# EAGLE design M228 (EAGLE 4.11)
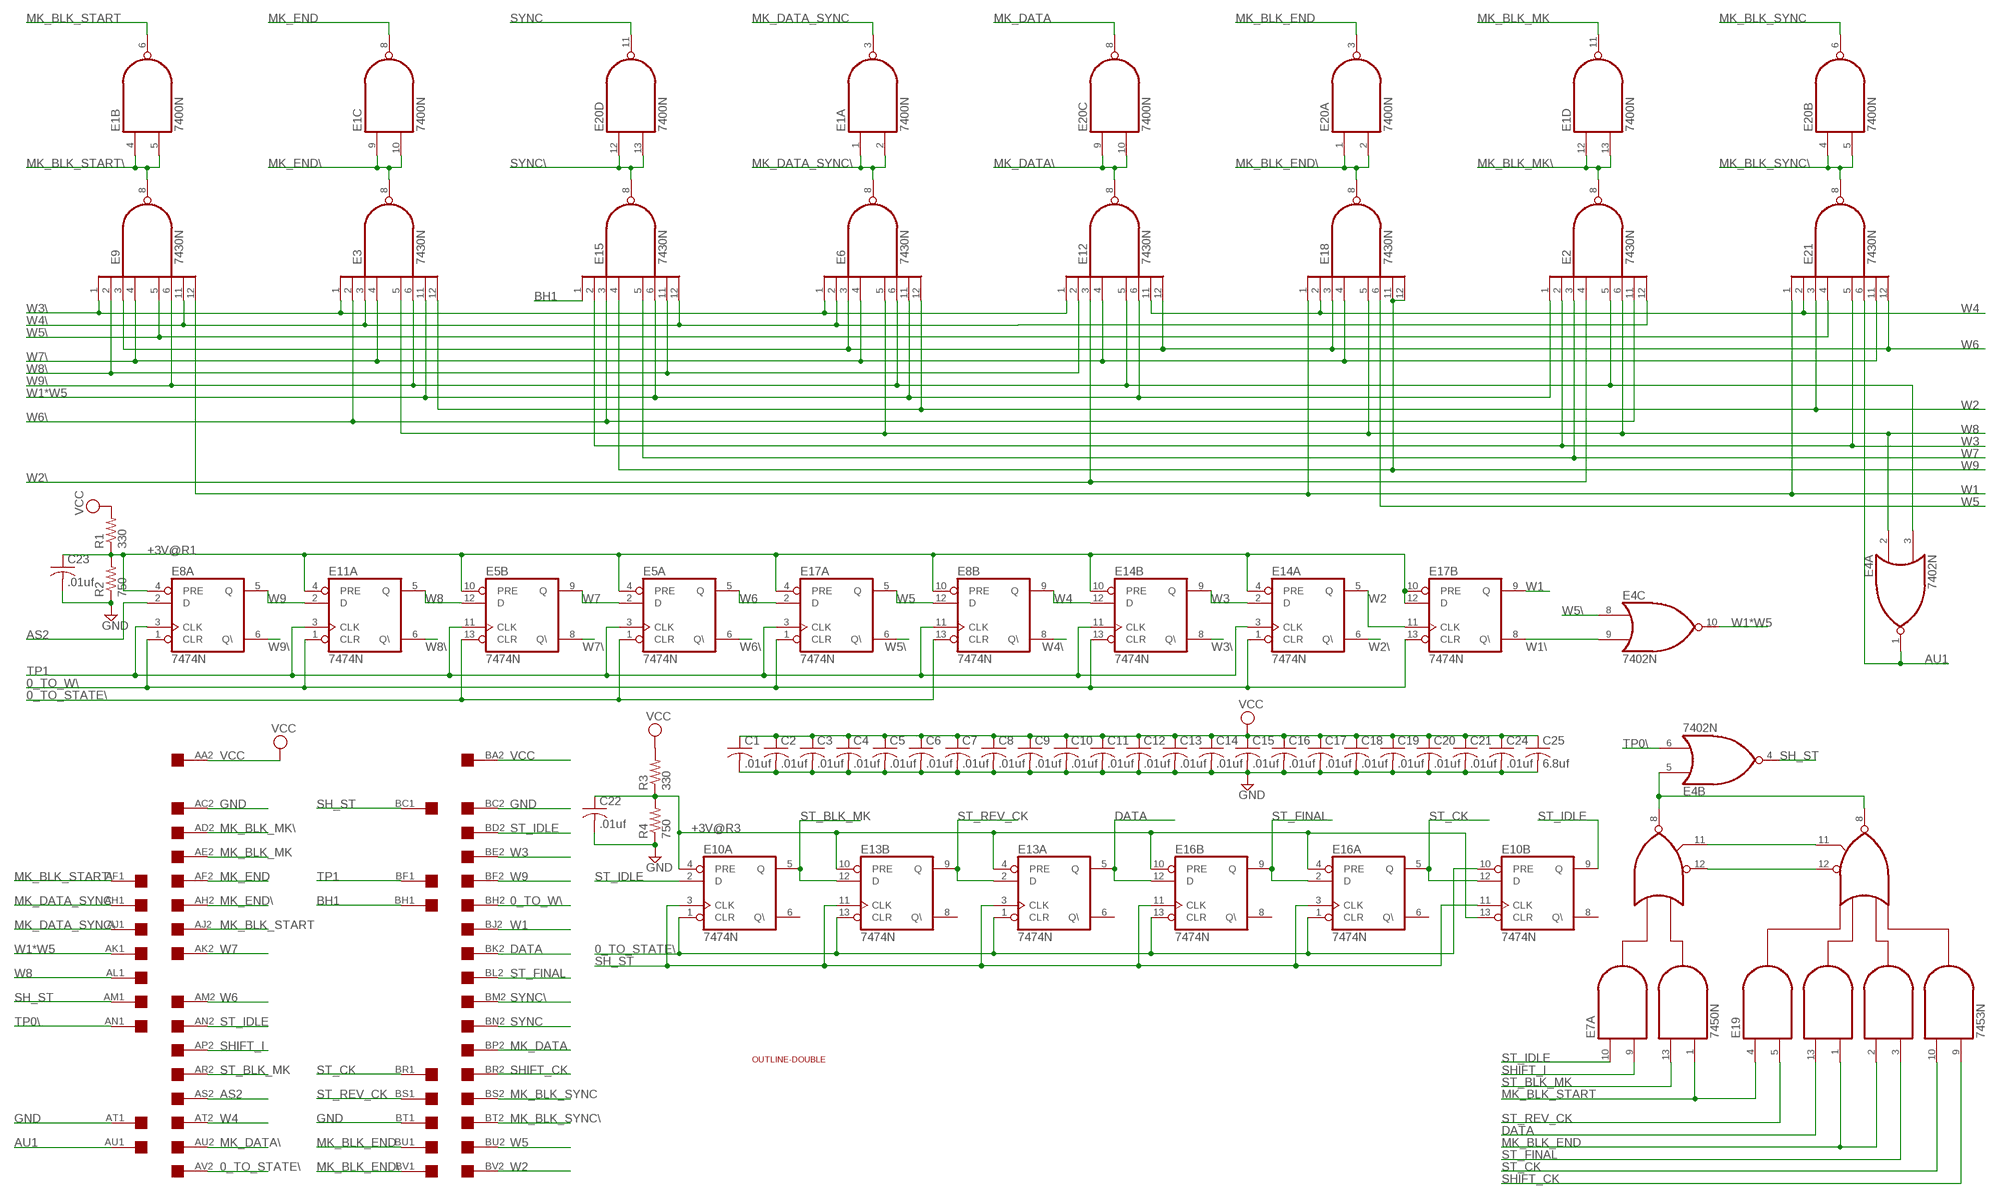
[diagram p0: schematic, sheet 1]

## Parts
C1  .01uf  C-US050-025X075  [C050-025X075]
C2  .01uf  C-US050-025X075  [C050-025X075]
C3  .01uf  C-US050-025X075  [C050-025X075]
C4  .01uf  C-US050-025X075  [C050-025X075]
C5  .01uf  C-US050-025X075  [C050-025X075]
C6  .01uf  C-US050-025X075  [C050-025X075]
C7  .01uf  C-US050-025X075  [C050-025X075]
C8  .01uf  C-US050-025X075  [C050-025X075]
C9  .01uf  C-US050-025X075  [C050-025X075]
C10  .01uf  C-US050-025X075  [C050-025X075]
C11  .01uf  C-US050-025X075  [C050-025X075]
C12  .01uf  C-US050-025X075  [C050-025X075]
C13  .01uf  C-US050-025X075  [C050-025X075]
C14  .01uf  C-US050-025X075  [C050-025X075]
C15  .01uf  C-US050-025X075  [C050-025X075]
C16  .01uf  C-US050-025X075  [C050-025X075]
C17  .01uf  C-US050-025X075  [C050-025X075]
C18  .01uf  C-US050-025X075  [C050-025X075]
C19  .01uf  C-US050-025X075  [C050-025X075]
C20  .01uf  C-US050-025X075  [C050-025X075]
C21  .01uf  C-US050-025X075  [C050-025X075]
C22  .01uf  C-US050-025X075  [C050-025X075]
C23  .01uf  C-US050-025X075  [C050-025X075]
C24  .01uf  C-US050-025X075  [C050-025X075]
C25  6.8uf  C-US150-054X183  [C150-054X183]
E1  7400N  [DIL14]
E2  7430N  [DIL14]
E3  7430N  [DIL14]
E4  7402N  [DIL14]
E5  7474N  74S74N  [DIL14]
E6  7430N  [DIL14]
E7  7450N  [DIL14]
E8  7474N  74S74N  [DIL14]
E9  7430N  [DIL14]
E10  7474N  74S74N  [DIL14]
E11  7474N  74S74N  [DIL14]
E12  7430N  [DIL14]
E13  7474N  74S74N  [DIL14]
E14  7474N  74S74N  [DIL14]
E15  7430N  [DIL14]
E16  7474N  74S74N  [DIL14]
E17  7474N  74S74N  [DIL14]
E18  7430N  [DIL14]
E19  7453N  [DIL14]
E20  7400N  [DIL14]
E21  7430N  [DIL14]
R1  330  R-US_0207/10  [0207/10]
R2  750  R-US_0207/10  [0207/10]
R3  330  R-US_0207/10  [0207/10]
R4  750  R-US_0207/10  [0207/10]
U$1  OUTLINE-DOUBLE  [DOUBLE]
U$5  DOUBLE  [EDGE-CON4]

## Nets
0_TO_STATE\: E5.1(A:CLR) E5.13(B:CLR) E8.13(B:CLR) E10.1(A:CLR) E10.10(B:PRE) E13.1(A:CLR) E13.13(B:CLR) E16.1(A:CLR) E16.13(B:CLR) U$5.AV2
0_TO_W\: E8.1(A:CLR) E11.1(A:CLR) E14.1(A:CLR) E14.13(B:CLR) E17.1(A:CLR) E17.13(B:CLR) U$5.BH2
+3V@R1: C23.1 E5.4(A:PRE) E5.10(B:PRE) E8.4(A:PRE) E8.10(B:PRE) E11.4(A:PRE) E14.4(A:PRE) E14.10(B:PRE) E17.4(A:PRE) E17.10(B:PRE) E17.12(B:D) R1.1 R2.2
+3V@R3: C22.1 E10.4(A:PRE) E10.13(B:CLR) E13.4(A:PRE) E13.10(B:PRE) E16.4(A:PRE) E16.10(B:PRE) R3.1 R4.2
AS2: E8.2(A:D) U$5.AS2
AU1: E4.1(A:O) E21.6(I5) U$5.AU1
BH1: E15.1(I0) U$5.BH1
DATA: E13.5(A:Q) E16.12(B:D) E19.13(I3) U$5.BK2
GND: C1.2 C2.2 C3.2 C4.2 C5.2 C6.2 C7.2 C8.2 C9.2 C10.2 C11.2 C12.2 C13.2 C14.2 C15.2 C16.2 C17.2 C18.2 C19.2 C20.2 C21.2 C22.2 C23.2 C24.2 C25.2 R2.1 R4.1 U$5.AC2 U$5.AT1 U$5.BC2 U$5.BT1
MK_BLK_END: E19.1(I4) E19.2(I5) E20.3(A:O) U$5.BU1
MK_BLK_END\: E18.8(O) E20.1(A:I0) E20.2(A:I1) U$5.BV1
MK_BLK_MK: E1.11(D:O) U$5.AE2
MK_BLK_MK\: E1.12(D:I0) E1.13(D:I1) E2.8(O) U$5.AD2
MK_BLK_START: E1.6(B:O) E7.1(A:I4) E19.4(I1) U$5.AJ2
MK_BLK_START\: E1.4(B:I0) E1.5(B:I1) E9.8(O) U$5.AF1
MK_BLK_SYNC: E20.6(B:O) U$5.BS2
MK_BLK_SYNC\: E20.4(B:I0) E20.5(B:I1) E21.8(O) U$5.BT2
MK_DATA: E20.8(C:O) U$5.BP2
MK_DATA\: E12.8(O) E20.9(C:I0) E20.10(C:I1) U$5.AU2
MK_DATA_SYNC: E1.3(A:O) U$5.AH1
MK_DATA_SYNC\: E1.1(A:I0) E1.2(A:I1) E6.8(O) U$5.AJ1
MK_END: E1.8(C:O) U$5.AF2
MK_END\: E1.9(C:I0) E1.10(C:I1) E3.8(O) U$5.AH2
N$1: E7.12(A:I5) E19.12(I9)
N$2: E7.11(A:I6) E19.11(I10)
N$3: E4.5(B:I0) E7.8(A:O) E19.8(O)
SH_ST: E4.4(B:O) E10.3(A:CLK) E10.11(B:CLK) E13.3(A:CLK) E13.11(B:CLK) E16.3(A:CLK) E16.11(B:CLK) U$5.AM1 U$5.BC1
SHIFT_CK: E19.9(I8) U$5.BR2
SHIFT_I: E7.9(A:I2) U$5.AP2
ST_BLK_MK: E7.13(A:I3) E10.5(A:Q) E13.12(B:D) U$5.AR2
ST_CK: E10.12(B:D) E16.5(A:Q) E19.10(I7) U$5.BR1
ST_FINAL: E16.2(A:D) E16.9(B:Q) E19.3(I6) U$5.BL2
ST_IDLE: E7.10(A:I1) E10.2(A:D) E10.9(B:Q) U$5.AN2 U$5.BD2
ST_REV_CK: E13.2(A:D) E13.9(B:Q) E19.5(I2) U$5.BS1
SYNC: E20.11(D:O) U$5.BN2
SYNC\: E15.8(O) E20.12(D:I0) E20.13(D:I1) U$5.BM2
TP0\: E4.6(B:I1) U$5.AN1
TP1: E5.3(A:CLK) E5.11(B:CLK) E8.3(A:CLK) E8.11(B:CLK) E11.3(A:CLK) E14.3(A:CLK) E14.11(B:CLK) E17.3(A:CLK) U$5.BF1
VCC: C1.1 C2.1 C3.1 C4.1 C5.1 C6.1 C7.1 C8.1 C9.1 C10.1 C11.1 C12.1 C13.1 C14.1 C15.1 C16.1 C17.1 C18.1 C19.1 C20.1 C21.1 C24.1 C25.1 R1.2 R3.2 U$5.AA2 U$5.BA2
W1: E9.12(I7) E17.9(B:Q) E18.1(I0) E21.1(I0) U$5.BJ2
W1*W5: E2.1(I0) E3.11(I6) E4.10(C:O) E6.11(I6) E12.6(I5) E15.6(I5) U$5.AK1
W1\: E4.9(C:I1) E17.8(B:Q\)
W2: E3.12(I7) E6.12(I7) E14.5(A:Q) E17.11(B:CLK) E21.3(I2) U$5.BV2
W2\: E2.4(I3) E12.3(I2) E14.6(A:Q\)
W3: E2.2(I1) E14.2(A:D) E14.9(B:Q) E15.2(I1) E21.5(I4) U$5.BE2
W3\: E3.1(I0) E6.1(I0) E9.1(I0) E12.1(I0) E14.8(B:Q\)
W4: E8.9(B:Q) E12.11(I6) E14.12(B:D) E18.2(I1) E21.2(I1) U$5.AT2
W4\: E2.12(I7) E3.3(I2) E6.2(I1) E8.8(B:Q\) E9.11(I6) E15.12(I7)
W5: E8.12(B:D) E17.5(A:Q) E18.6(I5) U$5.BU2
W5\: E4.8(C:I0) E9.5(I4) E17.6(A:Q\) E21.4(I3)
W6: E5.5(A:Q) E6.3(I2) E9.3(I2) E12.12(I7) E17.2(A:D) E18.3(I2) E21.12(I7) U$5.AM2
W6\: E2.11(I6) E3.2(I1) E5.6(A:Q\) E15.3(I2)
W7: E2.3(I2) E5.2(A:D) E5.9(B:Q) E15.5(I4) U$5.AK2
W7\: E3.4(I3) E5.8(B:Q\) E6.4(I3) E9.4(I3) E12.4(I3) E18.4(I3) E21.11(I6)
W8: E2.6(I5) E3.5(I4) E4.2(A:I0) E5.12(B:D) E6.5(I4) E11.5(A:Q) E18.5(I4) U$5.AL1
W8\: E9.2(I1) E11.6(A:Q\) E12.2(I1) E15.11(I6)
W9: E8.5(A:Q) E11.2(A:D) E15.4(I3) E18.11(I6) E18.12(I7) U$5.BF2
W9\: E2.5(I4) E3.6(I5) E4.3(A:I1) E6.6(I5) E8.6(A:Q\) E9.6(I5) E12.5(I4)
Unconnected: E4.11(D:I0) E4.12(D:I1) E4.13(D:O) E7.2(B:I1) E7.3(B:I2) E7.4(B:I3) E7.5(B:I4) E7.6(B:O) E10.6(A:Q\) E10.8(B:Q\) E11.8(B:Q\) E11.9(B:Q) E11.10(B:PRE) E11.11(B:CLK) E11.12(B:D) E11.13(B:CLR) E13.6(A:Q\) E13.8(B:Q\) E16.6(A:Q\) E16.8(B:Q\) U$5.AA1 U$5.AB1 U$5.AB2 U$5.AC1 U$5.AD1 U$5.AE1 U$5.AL2 U$5.AP1 U$5.AR1 U$5.AS1 U$5.AV1 U$5.BA1 U$5.BB1 U$5.BB2 U$5.BD1 U$5.BE1 U$5.BJ1 U$5.BK1 U$5.BL1 U$5.BM1 U$5.BN1 U$5.BP1

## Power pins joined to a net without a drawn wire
GND: E1.7(P:GND) E2.7(GND) E3.7(GND) E4.7(P:GND) E5.7(P:GND) E6.7(GND) E7.7(P:GND) E8.7(P:GND) E9.7(GND) E10.7(P:GND) E11.7(P:GND) E12.7(GND) E13.7(P:GND) E14.7(P:GND) E15.7(GND) E16.7(P:GND) E17.7(P:GND) E18.7(GND) E19.7(GND) E20.7(P:GND) E21.7(GND)
VCC: E1.14(P:VCC) E2.14(VCC) E3.14(VCC) E4.14(P:VCC) E5.14(P:VCC) E6.14(VCC) E7.14(P:VCC) E8.14(P:VCC) E9.14(VCC) E10.14(P:VCC) E11.14(P:VCC) E12.14(VCC) E13.14(P:VCC) E14.14(P:VCC) E15.14(VCC) E16.14(P:VCC) E17.14(P:VCC) E18.14(VCC) E19.14(VCC) E20.14(P:VCC) E21.14(VCC)

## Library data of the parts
C1-C25 = rcl:C-US: CAPACITOR, American symbol
E1 E20 = 74xx-us:74*00: Quad 2-input NAND gate
E2 E3 E6 E9 E12 E15 E18 E21 = 74xx-us:74*30: 8-input NAND gate
E4 = 74xx-us:74*02: Quad 2-input NOR gate
E5 E8 E10 E11 E13 E14 E16 E17 = 74xx-us:74*74: Dual D type positive edge triggered FLIP FLOP, preset and clear
E7 = 74xxN:74*50: 4-2-3-2 input AND OR INVERTER gates
E19 = 74xxN:74*53: 4-2-3-2 input AND OR INVERTER gates
R1-R4 = rcl:R-US_: RESISTOR, American symbol
U$1 = dec-con:OUTLINE-*: Board outlines for DEC boards.
U$5 = dec-con:DOUBLE: Double-Height DEC board

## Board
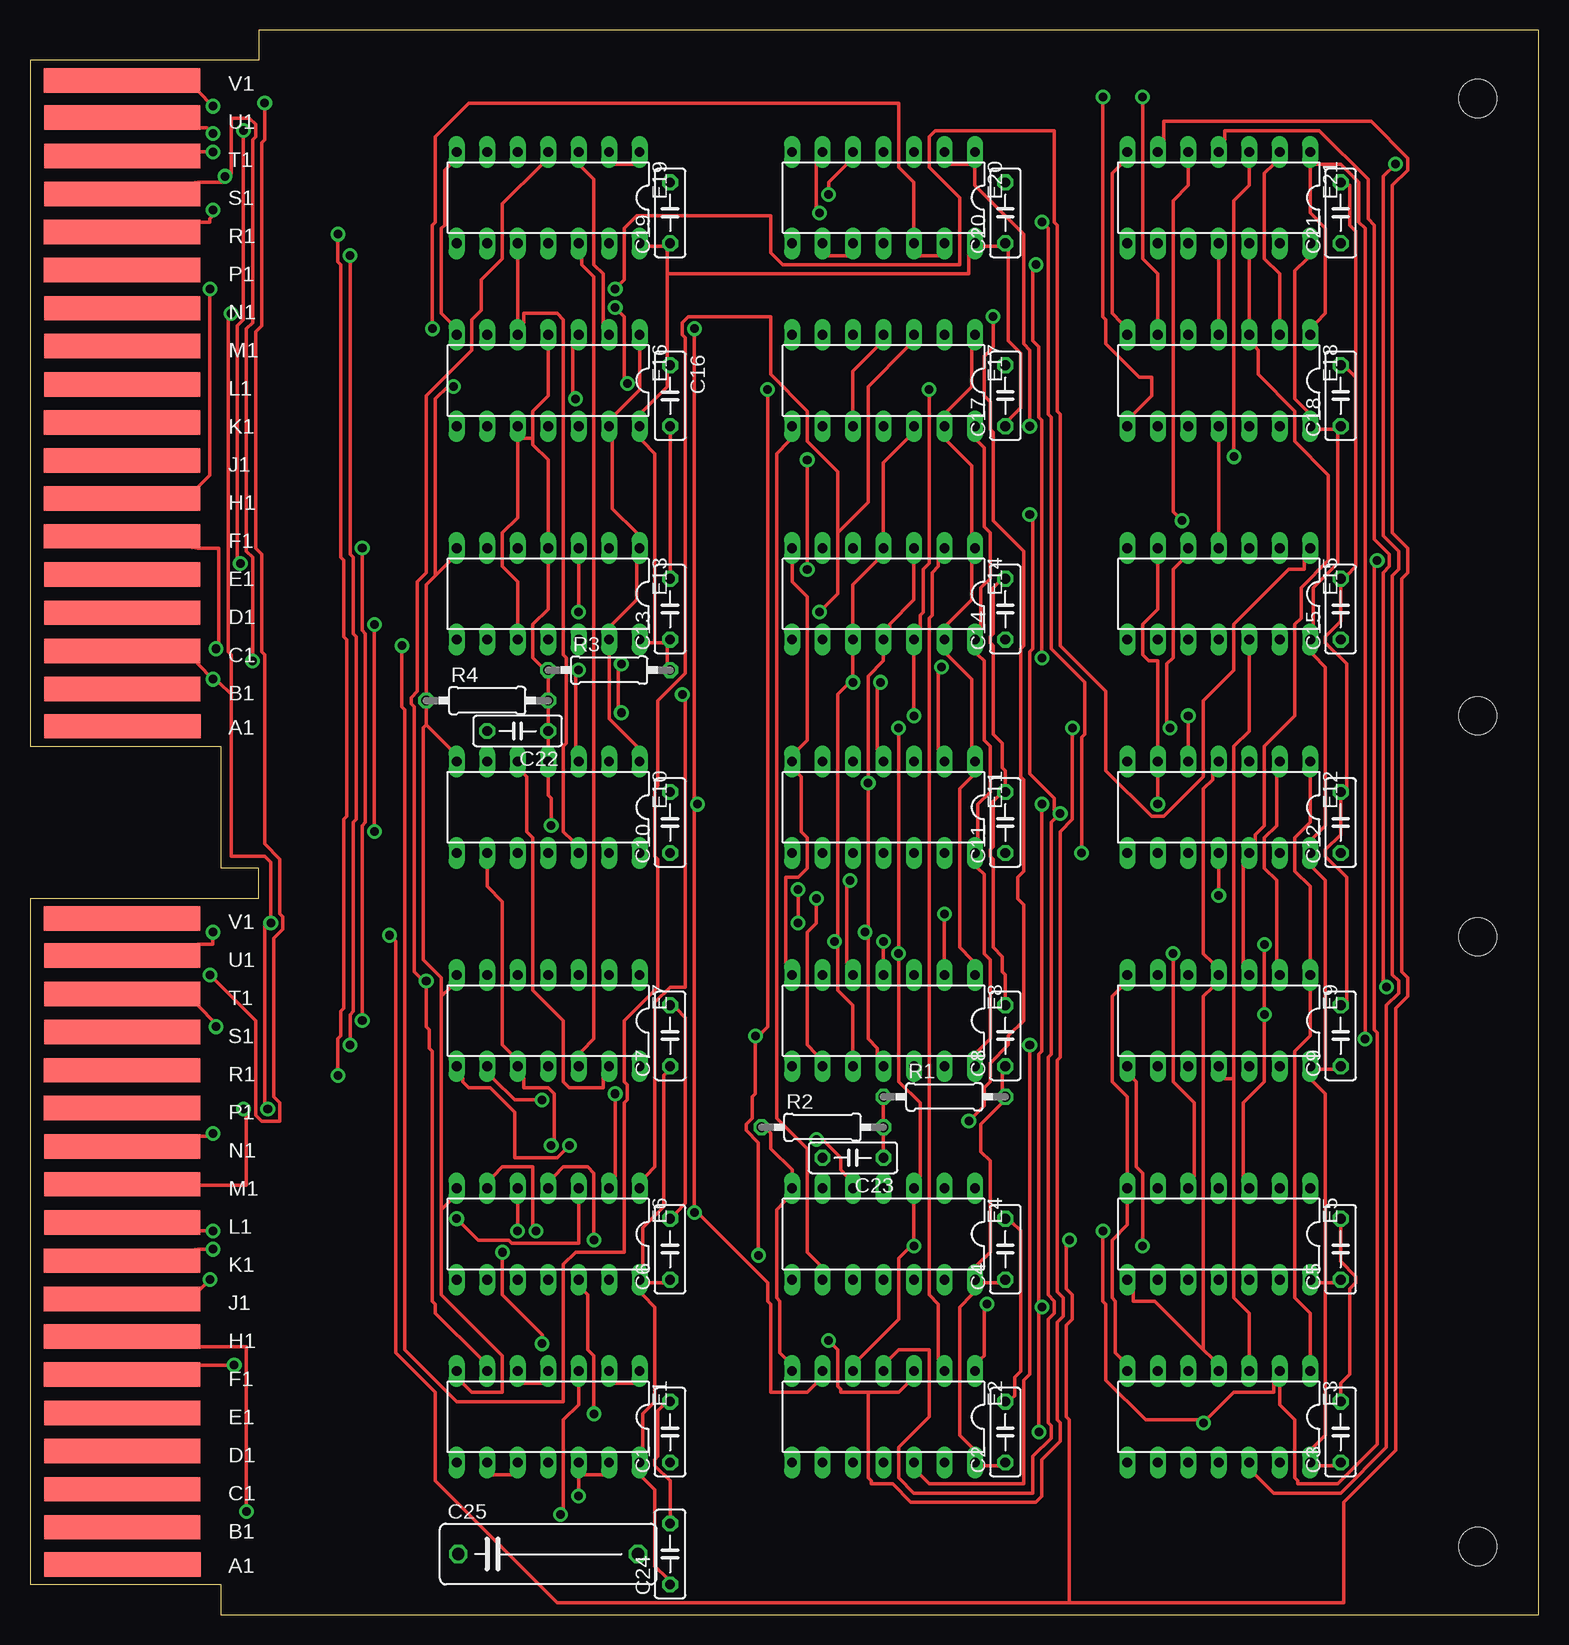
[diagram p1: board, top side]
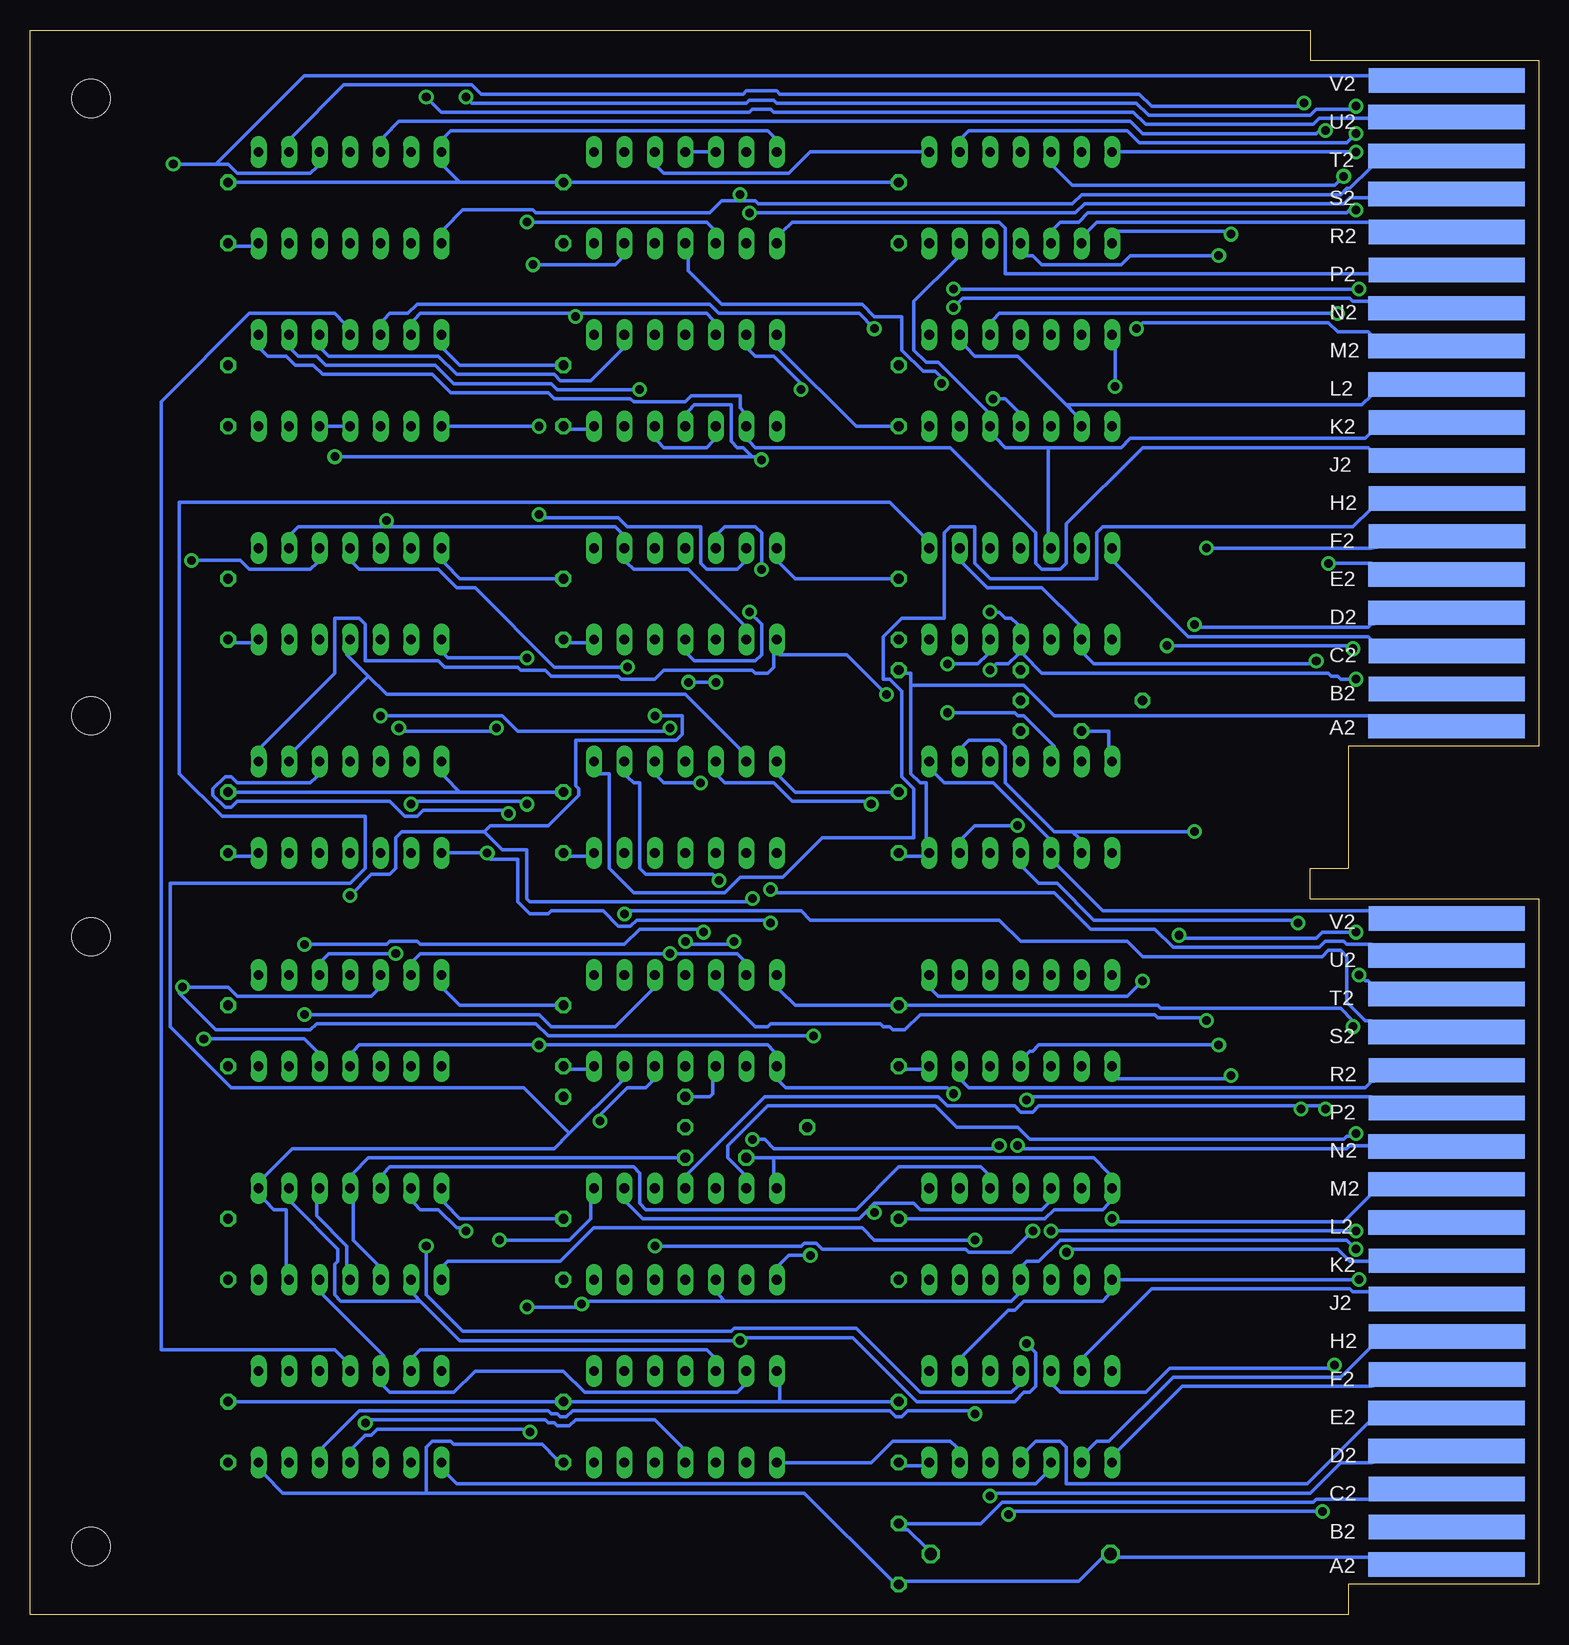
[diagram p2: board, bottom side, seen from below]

Size 125.73 x 132.08 mm. Coordinates in mm from the lower left corner, seen from the top.
Copper layers (1*16): Top 0.035mm / dielectric 1.5mm / Bottom 0.035mm
Design rules "10mils": minimum track width 12mil, minimum drill 28mil, track to track 10mil, track to pad 10mil, pad to pad 10mil, via to via 10mil, smd to smd 10mil, copper to edge 25mil, drill to drill 10mil, minimum pad ring 10mil, minimum via ring 10mil, stop-mask expansion 0mil, vias tented up to drill 0mil, thermal gap 10mil
vRestrict: area 31.8,108 to 41.9,125.7; area 49.5,108 to 59.7,125.7; area 67.3,108 to 77.5,125.7; area 85.1,108 to 95.3,125.7; area 102.9,108 to 113,125.7; area 31.8,80 to 41.9,97.8; area 49.5,80 to 59.7,97.8; area 67.3,80 to 77.5,97.8; area 85.1,80 to 95.3,97.8; area 31.8,34.3 to 41.9,52.1; area 49.5,34.3 to 59.7,52.1; area 67.3,34.3 to 77.5,52.1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

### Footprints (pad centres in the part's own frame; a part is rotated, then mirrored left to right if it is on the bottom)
C050-025X075 = drill 0.813 octagon: 1 -2.54,0; 2 2.54,0
C150-054X183 = drill 1.016 octagon: 1 -7.493,0; 2 7.493,0
DIL14 = drill 0.813 long: 1 -7.62,-3.81; 2 -5.08,-3.81; 3 -2.54,-3.81; 4 0,-3.81; 5 2.54,-3.81; 6 5.08,-3.81; 7 7.62,-3.81; 8 7.62,3.81; 9 5.08,3.81; 10 2.54,3.81; 11 0,3.81; 12 -2.54,3.81; 13 -5.08,3.81; 14 -7.62,3.81
0207/10 = drill 0.813 octagon: 1 -5.08,0; 2 5.08,0
DOUBLE = hole 3.175: 120.65,56.515; 120.65,5.715; 120.65,74.93; 120.65,126.365
EDGE-CON4 = smd 13.017 x 2.032: AA1 7.709,4.207; AB1 7.684,7.312; AC1 7.684,10.474; AD1 7.684,13.665; AE1 7.693,16.84; AF1 7.668,20.041; AH1 7.668,23.19; AJ1 7.668,26.34; AK1 7.668,29.515; AL1 7.693,32.69; AM1 7.693,35.89; AN1 7.693,39.04; AP1 7.668,42.24; AR1 7.668,45.39; AS1 7.693,48.565; AT1 7.693,51.74; AU1 7.693,54.94; AV1 7.668,58.026; BA1 7.709,74.057; BB1 7.684,77.162; BC1 7.684,80.324; BD1 7.684,83.515; BE1 7.693,86.69; BF1 7.668,89.891; BH1 7.668,93.04; BJ1 7.668,96.19; BK1 7.668,99.365; BL1 7.693,102.54; BM1 7.693,105.74; BN1 7.693,108.89; BP1 7.668,112.09; BR1 7.668,115.24; BS1 7.693,118.415; BT1 7.693,121.59; BU1 7.693,124.79; BV1 7.668,127.876 | smd 13.017 x 2.032 bottom: AA2 7.69,4.207; AB2 7.668,7.328; AC2 7.668,10.49; AD2 7.693,13.665; AE2 7.693,16.84; AF2 7.642,20.041; AH2 7.642,23.19; AJ2 7.668,26.34; AK2 7.668,29.515; AL2 7.693,32.69; AM2 7.693,35.89; AN2 7.693,39.04; AP2 7.668,42.24; AR2 7.668,45.39; AS2 7.693,48.565; AT2 7.693,51.74; AU2 7.693,54.966; AV2 7.668,58.026; BA2 7.69,74.057; BB2 7.668,77.178; BC2 7.668,80.34; BD2 7.693,83.515; BE2 7.693,86.69; BF2 7.642,89.891; BH2 7.642,93.04; BJ2 7.668,96.19; BK2 7.668,99.365; BL2 7.693,102.54; BM2 7.693,105.74; BN2 7.693,108.89; BP2 7.668,112.09; BR2 7.668,115.24; BS2 7.693,118.415; BT2 7.693,121.59; BU2 7.693,124.816; BV2 7.668,127.876

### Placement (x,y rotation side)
C1  53.34,15.24 90 top
C2  81.28,15.24 90 top
C3  109.22,15.24 90 top
C4  81.28,30.48 90 top
C5  109.22,30.48 90 top
C6  53.34,30.48 90 top
C7  53.34,48.26 90 top
C8  81.28,48.26 90 top
C9  109.22,48.26 90 top
C10  53.34,66.04 90 top
C11  81.28,66.04 90 top
C12  109.22,66.04 90 top
C13  53.34,83.82 90 top
C14  81.28,83.82 90 top
C15  109.22,83.82 90 top
C16  53.34,101.6 270 top
C17  81.28,101.6 90 top
C18  109.22,101.6 90 top
C19  53.34,116.84 90 top
C20  81.28,116.84 90 top
C21  109.22,116.84 90 top
C22  40.64,73.66 180 top
C23  68.58,38.1 180 top
C24  53.34,5.08 90 top
C25  43.18,5.08 0 top
E1  43.18,16.51 180 top
E2  71.12,16.51 180 top
E3  99.06,16.51 180 top
E4  71.12,31.75 180 top
E5  99.06,31.75 180 top
E6  43.18,31.75 180 top
E7  43.18,49.53 180 top
E8  71.12,49.53 180 top
E9  99.06,49.53 180 top
E10  43.18,67.31 180 top
E11  71.12,67.31 180 top
E12  99.06,67.31 180 top
E13  43.18,85.09 180 top
E14  71.12,85.09 180 top
E15  99.06,85.09 180 top
E16  43.18,102.87 180 top
E17  71.12,102.87 180 top
E18  99.06,102.87 180 top
E19  43.18,118.11 180 top
E20  71.12,118.11 180 top
E21  99.06,118.11 180 top
R1  76.2,43.18 0 top
R2  66.04,40.64 0 top
R3  48.26,78.74 0 top
R4  38.1,76.2 0 top
U$1  0,0 0 top
U$5  0,0 0 top

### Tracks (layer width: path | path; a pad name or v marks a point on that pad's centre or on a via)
0_TO_STATE\
  Top 0.305: E16.1 50.8,105.41 50.8,102.11 48.77,100.08 E16.13 48.51,97.79 48.51,92.2 50.55,90.17 E13.1 50.55,87.63 50.55,84.58 48.51,82.55 E13.13 48.26,80.01 48.26,74.68 50.55,72.39 E10.1
  Bottom 0.305: E5.13 104.39,29.21 104.39,33.78 105.41,33.78 106.17,34.54 E5.1 106.17,36.58 103.89,38.86 82.04,38.86 80.77,40.13 | 80.77,40.13 76.45,44.45 E8.13 | E10.1 50.29,70.1 49.53,69.34 45.47,69.34 40.89,64.77 E10.10 40.13,62.48 36.32,58.67 13.97,58.67 U$5.AV2 | 80.77,40.13 84.58,43.94 108.97,43.94 114.05,49.02 114.05,60.96 99.06,60.96 97.79,62.23 97.79,66.55 109.73,66.55 113.28,70.1 113.28,92.71 54.1,92.71 51.31,89.92 E13.1
0_TO_W\
  Top 0.305: E17.1 78.49,105.41 78.49,102.36 76.45,100.33 E17.13 76.45,97.79 78.49,95.76 78.49,90.17 E14.1 78.49,87.63 78.49,84.58 76.45,82.55 E14.13 76.45,80.01 78.49,77.98 78.49,72.39 E11.1 78.49,69.85 77.47,68.83 77.47,55.63 78.49,54.61 E8.1
  Bottom 0.305: U$5.BH2 13.97,92.2 15.49,90.68 36.32,90.68 36.83,90.17 36.83,86.36 45.72,86.36 46.99,87.63 46.99,90.68 49.02,90.68 49.53,90.17 49.53,83.06 53.09,83.06 54.61,81.53 54.61,77.98 54.1,77.98 53.09,76.96 53.09,69.85 52.07,68.83 52.07,64.77 59.69,64.77 62.99,61.47 66.55,61.47 67.82,60.2 75.44,60.2 77.47,62.23 77.47,70.1 78.23,70.1 E11.1
+3V@R1  (via drill 0.71)
  Top 0.305: E17.4 70.61,105.66 68.58,103.63 68.58,100.33 E17.10 | v70.87,77.72 70.61,77.47 70.61,72.14 E11.4 | E17.12 73.15,98.04 71.12,96.01 71.12,90.17 E14.4 70.61,87.88 68.58,85.85 68.58,82.55 E14.10 68.58,80.01 v68.58,77.72 68.07,77.47 67.31,76.71 67.31,56.64 v67.06,56.13 67.31,55.88 67.31,52.07 68.58,50.8 68.58,46.99 E8.10 | C23.1 71.12,38.61 71.12,40.13 R2.2 71.12,41.15 71.12,42.67 R1.1 | v71.12,56.13 71.12,54.61 E8.4
  Bottom 0.305: E17.10 68.83,97.79 69.34,97.28 72.9,97.28 73.41,97.79 E17.12 | v68.58,77.72 v70.87,77.72 | E5.10 96.77,29.21 98.81,31.24 98.81,34.29 E5.4 98.81,36.83 97.54,38.1 71.63,38.1 C23.1 | E8.10 68.83,44.45 68.83,43.43 69.09,43.18 70.61,43.18 R1.1 | v71.12,56.13 70.87,55.88 67.31,55.88 v67.06,56.13
+3V@R3  (via drill 0.71)
  Top 0.305: E13.10 40.64,82.55 40.64,86.11 39.37,87.38 39.37,90.17 40.64,91.44 40.64,97.79 E16.10 41.15,98.04 41.91,98.04 | 41.91,98.04 41.91,97.54 43.18,96.27 43.18,90.17 E13.4 43.18,87.63 43.18,83.82 41.91,82.55 41.91,79.76 42.67,78.99 R3.1 43.18,78.23 43.18,76.71 R4.2 43.18,75.69 43.18,74.17 C22.1 43.18,73.15 43.18,72.39 E10.4 43.18,69.85 43.18,68.33 43.43,68.07 v43.43,65.79 | 41.91,98.04 41.91,100.33 43.18,101.6 43.18,105.41 E16.4
  Bottom 0.305: v43.43,65.79 46.99,65.79 48.01,64.77 E10.13
AS2  (via drill 0.71)
  Top 0.305: v76.2,58.42 76.2,54.61 E8.2
  Bottom 0.305: v76.2,58.42 75.95,58.67 61.47,58.67 60.71,57.91 44.96,57.91 43.18,56.13 34.29,56.13 33.02,54.86 18.03,54.86 17.53,55.37 16.51,55.37 16,54.86 16,51.05 14.48,49.53 13.97,49.53 U$5.AS2
AU1  (via drill 0.71)
  Top 0.305: v15.24,56.9 15.24,55.88 13.97,55.88 U$5.AU1 | v29.97,56.64 30.48,56.13 30.48,21.84 33.78,18.54 33.78,11.18 43.94,1.02 86.61,1.02 | 86.61,1.02 109.47,1.02 109.47,9.4 113.79,13.72 113.79,50.55 114.81,51.56 114.81,53.09 114.3,53.59 114.3,86.36 114.81,86.87 114.81,88.9 113.54,90.17 113.54,119.13 114.81,120.4 114.81,121.41 111.76,124.46 94.49,124.46 94.49,122.94 E21.6 | v86.61,31.24 86.36,30.99 86.36,27.18 86.87,26.67 86.87,24.64 86.36,24.13 86.36,16.51 86.61,16.26 86.61,1.02
  Bottom 0.305: v15.24,56.9 18.03,56.9 18.54,56.39 29.72,56.39 v29.97,56.64 | v86.61,31.24 80.77,31.24 78.99,33.02 78.99,34.29 E4.1
BH1  (via drill 0.71)
  Top 0.305: v14.99,110.49 14.99,95 13.97,93.98 U$5.BH1 | v48.77,110.49 49.53,111.25 49.53,115.57 50.55,116.59 61.72,116.59 61.72,113.54 62.74,112.52 77.47,112.52 77.47,118.11 74.93,120.65 74.93,123.19 75.44,123.7 85.34,123.7 85.34,116.08 85.6,115.82 85.6,100.33 85.85,100.08 85.85,80.77 89.66,76.96 89.66,70.36 93.47,66.55 94.49,66.55 97.79,69.85 97.79,76.2 100.33,78.74 100.33,82.55 104.9,87.12 106.17,87.12 106.17,87.88 E15.1
  Bottom 0.305: v14.99,110.49 v48.77,110.49
DATA
  Bottom 0.305: 40.89,97.28 40.89,90.17 E13.5 | 40.89,97.28 44.45,97.28 45.21,98.04 E16.12 45.97,100.33 50.04,104.39 51.05,104.39 52.07,105.41 52.07,109.47 48.51,113.03 E19.13 | 40.89,97.28 34.8,97.28 34.04,98.04 14.48,98.04 13.97,98.55 U$5.BK2
GND  (via drill 0.71)
  Top 0.305: E16.7 35.05,107.7 34.29,108.46 34.29,115.57 34.54,115.82 34.54,120.4 35.05,120.9 E19.7 | v15.24,121.92 13.97,121.92 U$5.BT1 | C13.2 53.34,86.87 53.34,98.55 C16.2 | E14.7 63.5,87.63 63.5,86.11 64.77,84.84 64.77,72.9 64.01,72.14 E11.7 64.01,70.1 64.26,69.85 64.26,65.28 64.77,64.77 64.77,62.23 64.01,61.47 62.99,61.47 62.99,54.36 E8.7 | 33.02,74.17 33.02,75.69 R4.1 33.02,76.71 33.02,85.85 33.78,86.61 | 33.02,74.17 35.05,72.14 E10.7 | 33.78,86.61 35.05,87.88 E13.7 | 34.29,33.78 34.29,26.67 39.37,21.59 39.37,18.54 36.83,18.54 36.07,19.3 E1.7 | 34.29,33.78 35.05,34.54 E6.7 | 34.29,51.56 35.05,52.32 E7.7 | 34.29,33.78 34.29,51.56 | C7.2 53.85,50.55 54.61,49.78 54.61,34.29 53.85,33.53 53.85,33.27 C6.2 | 33.02,74.17 32.77,73.91 32.77,54.61 34.29,53.09 34.29,51.56 | v15.49,49.02 15.49,49.28 13.97,50.8 U$5.AT1 | v35.31,102.36 34.8,102.36 33.78,101.35 33.78,86.61 | 110.49,103.12 110.49,87.38 109.73,86.61 C15.2 109.22,85.85 109.22,82.8 107.95,81.53 107.95,81.03 109.73,79.25 109.73,68.83 C12.2 109.22,68.07 109.22,65.02 107.95,63.75 107.95,63.25 109.73,61.47 109.73,51.05 C9.2 | 110.49,103.12 109.73,103.89 C18.2 | 110.49,103.12 110.49,115.32 109.98,115.82 109.98,119.13 109.73,119.13 C21.2 | E18.7 90.93,107.7 90.17,108.46 90.17,120.14 90.93,120.9 E21.7 | C8.2 81.28,51.31 81.28,53.34 81.03,53.59 81.03,54.86 80.26,55.63 80.26,62.99 80.01,63.25 80.01,63.75 80.26,64.01 80.26,67.82 80.77,68.33 C11.2 81.28,69.09 81.28,70.36 81.03,70.61 81.03,72.64 80.26,73.41 80.26,80.77 80.01,81.03 80.01,81.53 80.26,81.79 80.26,85.6 80.77,86.11 C14.2 | E3.7 90.93,21.34 90.42,21.84 90.42,26.16 90.17,26.42 90.17,31.24 91.44,32.51 91.44,34.29 E5.7 91.44,36.83 91.44,43.18 90.17,44.45 90.17,51.56 90.93,52.32 E9.7
  Top 0.305: R2.1 61.47,40.39 61.72,40.13 61.72,38.86 63.5,37.08 63.5,36.83 E4.7 62.99,34.54 62.23,33.78 62.23,26.42 62.48,26.16 62.48,21.84 62.99,21.34 E2.7 | C5.2 109.22,32.51 109.22,29.46 110.49,28.19 110.49,27.69 109.98,27.18 109.98,20.07 109.22,19.3 109.22,18.29 C3.2 | C4.2 81.79,32.77 82.55,32 82.55,20.32 82.04,19.81 82.04,18.29 81.79,18.03 C2.2 | C24.2 53.34,8.13 53.34,11.18 52.07,12.45 52.07,12.95 52.32,13.21 52.32,17.02 52.83,17.53 C1.2
  Bottom 0.305: v15.24,121.92 35.05,121.92 E19.7 | C10.2 53.85,68.58 61.98,68.58 63.25,69.85 E11.7 | E14.7 63.25,87.63 61.98,86.36 53.85,86.36 C13.2 | E17.7 63.25,105.41 56.9,99.06 53.85,99.06 C16.2 | E10.7 35.81,72.39 35.81,73.66 37.59,73.66 C22.2 | E8.7 63.25,52.07 61.98,50.8 53.85,50.8 C7.2 52.83,50.8 31.75,50.8 31.5,50.55 16.51,50.55 15.49,49.53 v15.49,49.02 | C6.2 52.83,33.02 41.15,33.02 40.39,33.78 36.32,33.78 35.81,34.29 E6.7 35.81,36.83 37.08,38.1 63.75,38.1 | U$5.BC2 13.97,81.28 14.22,81.53 29.21,81.53 35.31,87.63 E13.7 | v35.31,102.36 35.31,105.41 E16.7 | C19.2 53.85,119.38 80.77,119.38 C20.2 81.79,119.38 89.92,119.38 | C17.2 81.79,104.14 89.92,104.14 91.19,105.41 E18.7 | E20.7 63.75,123.19 64.26,123.7 90.68,123.7 91.19,123.19 E21.7 91.19,120.65 89.92,119.38 | 89.92,119.38 108.71,119.38 C21.2 | U$5.AC2 13.97,9.65 18.54,9.65 18.8,9.4 44.7,9.4 46.48,7.62 52.83,7.62 C24.2 53.09,7.11 52.58,7.11 51.05,5.59 C25.2 | C14.2 81.79,86.36 89.92,86.36 91.19,87.63 E15.7 | C8.2 81.79,50.8 89.92,50.8 91.19,52.07 E9.7 | 89.92,68.58 81.79,68.58 C11.2 | 89.92,68.58 91.19,69.85 E12.7 | 89.92,68.58 108.71,68.58 C12.2 | C4.2 81.79,33.02 89.92,33.02 91.19,34.29 E5.7 | 63.75,38.1 63.75,36.83 E4.7 | 63.75,38.1 65.53,38.1 C23.2 | 63.25,17.78 80.77,17.78 C2.2 81.79,17.78 108.71,17.78 C3.2 | 63.25,17.78 53.85,17.78 C1.2 | 63.25,17.78 63.25,19.05 E2.7
MK_BLK_END  (via drill 0.71)
  Top 0.305: E19.1 50.29,120.9 48.77,120.9 E19.2 | v15.24,123.44 14.73,123.95 13.97,123.95 U$5.BU1
  Bottom 0.305: E20.3 73.41,120.65 72.9,120.14 62.48,120.14 60.71,121.92 51.31,121.92 E19.1 | v15.24,123.44 16,122.68 33.27,122.68 34.29,123.7 47.5,123.7 48.01,123.19 E19.2
MK_BLK_END\  (via drill 0.71)
  Top 0.305: E20.2 76.71,120.9 78.23,120.9 E20.1 78.74,120.65 78.74,119.13 82.8,115.06 82.8,105.92 83.31,105.41 v83.31,99.06 | v15.24,125.73 13.97,127 U$5.BV1 | v89.41,126.49 89.41,108.2 89.66,107.95 89.66,105.92 92.46,103.12 93.47,103.12 93.47,101.6 91.95,100.08 E18.8
  Bottom 0.305: v83.31,99.06 90.93,99.06 E18.8 | v15.24,125.73 15.49,125.48 18.54,125.48 19.05,124.97 32.51,124.97 33.53,125.98 63.5,125.98 63.75,126.24 65.79,126.24 66.04,125.98 88.9,125.98 v89.41,126.49
MK_BLK_MK
  Bottom 0.305: E1.11 42.67,13.72 41.91,14.48 39.88,14.48 39.37,13.97 39.37,10.92 19.3,10.92 14.22,16 13.97,16 U$5.AE2
MK_BLK_MK\  (via drill 0.71)
  Top 0.305: E1.13 47.75,11.68 46.23,11.68 E1.12 45.72,11.43 v45.72,9.91
  Bottom 0.305: E2.8 62.99,12.7 55.63,12.7 53.85,14.48 49.02,14.48 48.51,13.97 E1.13 | v45.72,9.91 45.47,10.16 19.05,10.16 16.51,12.7 13.97,12.7 U$5.AD2
MK_BLK_START  (via drill 0.71)
  Top 0.305: E1.6 37.59,21.34 33.78,25.15 33.78,25.91 33.53,26.16 33.53,46.99 33.27,47.24 33.27,48.77 33.02,49.02 v33.02,52.83 32.51,53.09 32,53.59 32,75.69 31.75,75.95 31.75,76.45 32.26,76.96 32.26,86.11 33.02,86.87 33.02,101.6 36.83,105.41 36.83,107.95 37.59,108.71 37.59,111.25 39.37,113.03 39.37,117.6 42.67,120.9 E19.4
  Bottom 0.305: U$5.AJ2 13.97,26.92 15.49,26.92 15.75,27.18 32.26,27.18 37.85,21.59 E1.6 | v33.02,52.83 34.29,51.56 50.04,51.56 50.55,52.07 E7.1
MK_BLK_START\  (via drill 0.71)
  Top 0.305: E1.4 42.67,19.3 41.15,19.3 E1.5 | v92.71,30.73 92.71,36.83 92.2,37.34 92.2,44.45 91.95,44.7 E9.8 | v17.02,20.83 13.97,20.83 U$5.AF1
  Bottom 0.305: v92.71,30.73 92.71,26.67 89.66,23.62 67.31,23.62 67.06,23.88 56.9,23.88 51.56,18.54 43.94,18.54 43.43,19.05 E1.4 | v17.02,20.83 17.27,20.57 30.73,20.57 32.77,18.54 39.88,18.54 40.39,19.05 E1.5
MK_BLK_SYNC  (via drill 0.71)
  Top 0.305: v65.79,116.84 65.53,117.09 65.53,120.9 E20.6
  Bottom 0.305: v65.79,116.84 38.61,116.84 37.85,117.6 16.26,117.6 15.75,118.11 13.97,118.11 U$5.BS2
MK_BLK_SYNC\  (via drill 0.71)
  Top 0.305: v66.55,118.36 66.55,119.38 68.07,120.9 E20.5
  Bottom 0.305: E20.5 69.09,121.92 70.61,121.92 E20.4 | 66.55,117.86 68.07,117.86 69.09,116.84 83.57,116.84 83.82,117.09 89.66,117.09 91.19,115.57 E21.8 | 66.55,117.86 65.28,117.86 65.02,117.6 38.86,117.6 38.1,118.36 16.51,118.36 16,118.87 15.75,118.87 13.97,120.65 U$5.BT2 | 66.55,117.86 v66.55,118.36
MK_DATA
  Bottom 0.305: E20.8 62.99,115.32 62.23,116.08 44.96,116.08 44.45,115.57 44.45,111.76 13.97,111.76 U$5.BP2
MK_DATA\  (via drill 0.71)
  Top 0.305: E20.10 68.07,113.28 66.55,113.28 E20.9 | v87.63,63.5 87.63,73.15 87.88,73.41 87.88,77.72 85.09,80.52 85.09,99.82 84.84,100.08 84.84,115.57 v84.33,116.08 | v64.01,60.45 v64.01,57.66
  Bottom 0.305: v84.33,116.08 69.34,116.08 68.83,115.57 E20.10 | E12.8 90.93,63.5 v87.63,63.5 87.38,62.99 85.09,62.99 85.09,59.44 84.07,58.42 82.55,58.42 82.3,58.67 77.98,58.67 76.71,57.4 75.69,57.4 75.18,57.91 64.26,57.91 v64.01,57.66 | v64.01,60.45 63.75,60.2 40.39,60.2 37.34,57.15 32,57.15 30.48,55.63 18.29,55.63 17.78,56.13 16.26,56.13 16,55.88 13.97,55.88 U$5.AU2
MK_DATA_SYNC  (via drill 0.71)
  Top 0.305: v18.03,8.64 18.03,22.35 13.97,22.35 U$5.AH1 | v44.2,8.38 44.45,8.64 44.45,16.26 45.72,17.53 45.72,19.05 E1.3
  Bottom 0.305: v18.03,8.64 43.94,8.64 v44.2,8.38
MK_DATA_SYNC\  (via drill 0.71)
  Top 0.305: E1.1 50.29,19.3 48.77,19.3 E1.2 | v14.99,27.94 13.97,26.92 U$5.AJ1
  Bottom 0.305: E1.2 48.01,21.59 44.2,25.4 43.69,25.4 42.93,26.16 36.32,26.16 35.81,26.67 E6.8 35.05,27.94 v14.99,27.94
MK_END
  Bottom 0.305: E1.8 35.05,13.72 29.72,19.05 13.97,19.05 U$5.AF2
MK_END\
  Top 0.305: E1.9 38.61,11.68 40.13,11.68 E1.10
  Bottom 0.305: E3.8 90.93,11.68 90.17,10.92 41.91,10.92 41.15,11.68 E1.10 | U$5.AH2 13.97,22.35 16.51,19.81 30.48,19.81 35.81,14.48 36.83,14.48 37.59,13.72 E1.9
N$1
  Top 0.305: E7.12 45.97,46.99 46.99,48.01 46.99,111.51 45.97,112.52 45.97,113.03 E19.12
N$2  (via drill 0.71)
  Top 0.305: v26.67,47.5 26.67,50.04 26.92,50.29 26.92,66.04 27.18,66.29 27.18,81.53 26.92,81.79 26.92,88.14 26.67,88.39 v26.67,113.28
  Bottom 0.305: v26.67,47.5 41.66,47.5 42.16,46.99 42.42,46.99 42.67,46.74 E7.11 | v26.67,113.28 34.04,113.28 34.8,112.52 41.4,112.52 42.16,113.28 42.67,113.28 E19.11
N$3  (via drill 0.71)
  Top 0.305: v25.65,44.96 25.65,48.01 25.91,48.26 25.91,50.29 26.16,50.55 26.16,66.29 26.42,66.55 26.42,81.28 26.16,81.53 26.16,87.88 25.91,88.14 25.91,112.52 25.65,112.78 v25.65,115.06 | v65.53,39.62 66.04,39.62 67.56,38.1 67.56,37.08 68.07,36.58 E4.5 | v44.96,39.12 43.94,38.1 40.39,38.1 40.39,41.91 38.35,43.94 36.58,43.94 36.07,44.45 36.07,44.7 E7.8
  Bottom 0.305: v25.65,44.96 25.91,44.7 35.05,44.7 E7.8 | v25.65,115.06 25.91,115.32 35.05,115.32 E19.8 | v65.53,39.62 64.52,39.62 63.75,38.86 45.21,38.86 v44.96,39.12
SH_ST  (via drill 0.71)
  Top 0.305: v45.47,101.35 45.21,101.6 45.21,105.66 E16.3 | U$5.BC1 13.97,79.5 13.97,79.25 v15.24,77.98 15.75,77.72 16.76,76.71 | 16.76,76.71 16.76,63.25 19.56,63.25 20.07,62.74 v20.07,57.66 19.56,57.4 19.56,42.42 v19.81,42.16 | v45.72,78.74 45.47,78.49 45.47,72.39 E10.3 | v45.72,83.57 45.72,87.63 E13.3 | v16.76,108.46 16.51,108.2 16.51,80.26 16.76,80.01 16.76,76.71 | v17.78,42.16 18.03,41.91 18.03,35.81 13.97,35.81 U$5.AM1
  Bottom 0.305: v45.47,101.35 44.45,101.35 43.43,100.33 E16.11 | v15.24,77.98 16.51,77.98 16.76,78.23 17.27,78.23 17.53,78.49 41.4,78.49 42.93,80.01 E13.11 | v20.07,57.66 20.32,57.91 37.08,57.91 40.13,60.96 41.66,60.96 42.93,62.23 E10.11 | v45.72,78.74 45.21,79.25 44.2,79.25 43.43,80.01 E13.11 | v45.72,83.57 44.96,83.57 44.45,83.06 43.94,83.06 43.43,82.55 E13.11 | E4.4 70.87,36.83 64.52,43.18 50.04,43.18 49.28,42.42 43.69,42.42 43.18,41.91 42.16,41.91 41.66,42.42 20.07,42.42 v19.81,42.16 19.3,42.42 18.03,42.42 v17.78,42.16 | v16.76,108.46 44.96,108.46 45.47,107.95 E16.3
SHIFT_CK
  Bottom 0.305: E19.9 37.59,115.32 36.83,116.08 13.97,116.08 U$5.BR2
SHIFT_I  (via drill 0.71)
  Top 0.305: v42.67,42.93 40.39,42.93 38.61,44.7 E7.9
  Bottom 0.305: v42.67,42.93 42.42,43.18 13.97,43.18 U$5.AP2
ST_BLK_MK  (via drill 0.71)
  Top 0.305: E10.5 41.15,70.1 41.4,69.85 41.4,65.28 41.91,64.77 41.91,52.07 44.45,49.53 44.45,44.45 44.96,43.94 47.75,43.94 47.75,44.7 E7.13 | v49.28,79.25 49.02,78.99 49.02,75.44 v49.28,75.18
  Bottom 0.305: U$5.AR2 13.97,44.45 14.48,43.94 47.5,43.94 48.01,44.45 E7.13 | v49.28,79.25 46.74,79.25 45.97,80.01 E13.12 | v49.28,75.18 43.69,75.18 43.43,74.93 42.93,74.93 40.39,72.39 E10.5
ST_CK  (via drill 0.71)
  Top 0.305: E10.12 45.21,64.52 44.45,65.28 44.45,72.39 44.7,72.64 44.7,79.76 44.45,80.01 44.45,107.95 43.94,108.46 41.15,108.46 41.15,107.7 E16.5 40.64,107.95 40.64,113.03 E19.10 | v15.24,117.09 15.24,116.59 14.99,116.33 14.99,116.08 13.97,116.08 U$5.BR1
  Bottom 0.305: v15.24,117.09 15.75,117.09 16,116.84 37.59,116.84 38.35,116.08 39.88,116.08 40.39,115.57 E19.10
ST_FINAL
  Top 0.305: E19.3 45.97,120.65 46.99,119.63 46.99,112.52 47.75,111.76 47.75,107.7 E16.2
  Bottom 0.305: 39.37,100.84 43.43,104.9 46.99,104.9 47.75,105.66 E16.2 | 39.37,100.84 38.61,100.08 E16.9 | 39.37,100.84 14.73,100.84 13.97,101.6 U$5.BL2
ST_IDLE  (via drill 0.71)
  Top 0.305: E10.9 38.1,62.23 38.1,60.71 39.37,59.44 39.37,47.5 40.13,46.74 E7.10 41.15,44.7 41.15,43.94 43.18,43.94 43.69,43.43 43.69,39.37 v43.43,39.12 | v28.7,65.28 v28.7,82.55
  Bottom 0.305: 38.86,65.28 40.39,65.28 44.45,69.34 44.45,72.39 44.96,72.9 47.5,72.9 48.01,72.39 E10.2 | 38.86,65.28 38.35,64.77 E10.9 | v43.43,39.12 43.18,38.86 16,38.86 15.75,39.12 13.97,39.12 U$5.AN2 | v28.7,82.55 28.45,82.3 14.22,82.3 13.97,82.55 U$5.BD2 | 38.86,65.28 v28.7,65.28
ST_REV_CK  (via drill 0.71)
  Top 0.305: U$5.BS1 13.97,119.38 16.26,119.38 v16.26,119.89 16.76,120.14 16.76,124.71 18.29,124.71 18.8,124.21 18.8,123.19 18.54,122.94 18.54,107.7 18.03,107.19 18.03,88.65 18.54,88.14 v18.54,79.5
  Bottom 0.305: v16.26,119.89 17.02,119.13 38.86,119.13 40.39,120.65 E19.5 | v18.54,79.5 18.8,79.25 37.08,79.25 37.85,80.01 E13.9 38.35,82.55 41.4,85.6 45.97,85.6 48.01,87.63 E13.2
SYNC  (via drill 0.71)
  Top 0.305: v48.77,108.97 49.53,108.2 49.53,102.87 v49.78,102.62
  Bottom 0.305: v48.77,108.97 48.01,109.73 15.75,109.73 15.49,109.47 13.97,109.47 U$5.BN2 | v49.78,102.62 49.78,103.12 50.29,103.63 51.31,103.63 53.09,105.41 53.09,108.2 55.37,108.2 56.39,109.22 68.07,109.22 70.87,112.01 70.87,113.03 E20.11
SYNC\  (via drill 0.71)
  Top 0.305: E20.13 75.69,113.28 74.17,113.28 E20.12 73.66,115.57 73.66,119.38 72.39,120.65 72.39,125.98 36.58,125.98 33.78,123.19 33.78,116.08 33.53,115.82 v33.53,107.19 | v84.33,79.76 84.33,99.57 84.07,99.82 84.07,105.66 83.57,106.17 83.57,112.27 v83.82,112.52
  Bottom 0.305: v84.33,79.76 90.93,79.76 91.19,80.01 E15.8 | v83.82,112.52 76.96,112.52 76.45,113.03 E20.13 | v33.53,107.19 33.02,107.7 17.53,107.7 16.76,106.93 14.22,106.93 13.97,106.68 U$5.BM2
TP0\  (via drill 0.71)
  Top 0.305: v15.24,40.13 14.99,39.88 13.97,39.88 U$5.AN1
  Bottom 0.305: v15.24,40.13 15.49,39.88 16,39.88 16.26,39.62 42.42,39.62 43.43,40.64 48.51,40.64 50.29,42.42 64.26,42.42 67.56,39.12 67.56,38.1 66.29,36.83 E4.6
TP1  (via drill 0.71)
  Top 0.305: E5.3 101.09,36.58 101.09,42.67 102.87,44.45 v102.87,50.04 102.87,50.55 v102.87,55.88 | 69.85,56.9 v69.85,69.34 69.85,78.23 71.12,79.5 71.12,80.01 E14.11 71.63,82.3 71.63,82.55 73.66,84.58 73.66,87.63 E14.3 | 69.85,56.9 69.85,48.01 70.61,47.24 70.61,46.74 E8.11 | 67.31,90.17 69.85,92.71 69.85,102.36 73.15,105.66 E17.3 | 67.31,90.17 67.31,85.09 v65.79,83.57 | v15.49,80.52 15.75,80.77 15.75,88.9 13.97,88.9 U$5.BF1 | v30.99,80.77 30.99,75.69 31.24,75.44 31.24,22.1 35.56,17.78 44.45,17.78 44.45,29.21 45.47,30.23 49.53,30.23 49.53,42.67 49.78,42.93 49.78,44.2 49.53,44.45 49.53,49.53 52.32,52.32 52.32,62.99 52.07,63.25 52.07,68.83 52.32,69.09 52.32,76.2 54.61,78.49 54.61,106.43 54.36,106.68 54.36,107.7 54.86,108.2 61.72,108.2 61.72,103.38 64.77,100.33 64.77,97.79 67.31,95.25 67.31,90.17 | 69.85,56.9 v69.6,56.9
  Bottom 0.305: v102.87,50.04 83.31,50.04 82.3,49.02 76.96,49.02 73.91,52.07 E8.3 | E5.11 99.31,29.21 99.31,30.73 101.85,33.27 101.85,34.29 E5.3 | v69.85,69.34 72.9,69.34 73.41,69.85 E11.3 | v65.79,83.57 64.77,82.55 64.77,80.01 65.28,79.5 70.36,79.5 70.87,80.01 E14.11 | v15.49,80.52 15.75,80.77 v30.99,80.77 | v102.87,55.88 96.01,55.88 95.76,56.13 93.47,56.13 93.22,55.88 76.2,55.88 74.93,57.15 69.85,57.15 v69.6,56.9
VCC
  Top 0.305: E19.14 51.31,114.05 52.83,114.05 C19.1 53.09,113.79 53.09,111.76 | 53.09,111.76 53.09,104.65 C16.1 53.09,103.63 53.09,102.36 51.05,100.33 E16.14 51.05,97.79 52.07,96.77 52.07,81.03 | R3.2 53.09,79.25 53.09,80.77 C13.1 52.83,81.03 52.07,81.03 | 52.07,81.03 51.31,81.03 E13.14 | C17.1 81.53,99.57 82.55,100.58 82.55,105.16 81.53,106.17 81.53,113.79 C20.1 80.77,114.05 79.25,114.05 E20.14 78.23,113.28 78.23,111.76 53.09,111.76 | C2.1 80.77,12.45 79.25,12.45 E2.14 78.49,13.97 77.47,14.99 77.47,25.65 78.49,26.67 E4.14 | E4.14 79.25,27.69 80.77,27.69 C4.1 | C8.1 81.03,45.21 81.03,43.69 R1.2 81.03,42.67 79.25,40.89 79.25,38.61 80.01,37.85 80.01,30.23 78.99,29.21 E4.14 | E8.14 78.99,46.99 80.01,48.01 80.01,54.61 79.5,55.12 79.5,61.72 78.99,62.23 E11.14 78.99,64.77 78.99,67.56 80.01,68.58 80.01,72.39 79.5,72.9 79.5,79.5 78.99,80.01 E14.14 79.25,82.3 79.25,85.6 80.01,86.36 80.01,90.17 79.5,90.68 79.5,97.28 78.99,97.79 E17.14 | E6.14 51.31,27.69 52.83,27.69 C6.1 | C24.1 53.09,3.05 52.07,4.06 52.07,10.41 51.05,11.43 E1.14 51.05,13.97 51.05,16.76 52.07,17.78 52.07,25.65 51.05,26.67 E6.14 | C7.1 53.09,45.21 52.83,44.96 52.83,34.04 51.05,32.26 51.05,29.21 E6.14 | E21.14 106.43,113.03 105.41,112.01 105.41,101.35 106.43,100.33 E18.14 107.19,98.81 108.71,98.81 C18.1 108.97,98.55 108.97,87.63 106.93,85.6 106.93,82.55 E15.14 106.93,80.01 107.95,78.99 107.95,65.79 106.93,64.77 E12.14 106.93,62.23 107.95,61.21 107.95,45.47 | 107.95,45.47 108.71,45.47 C9.1 | 107.95,45.47 107.19,45.47 E9.14 106.93,44.45 107.95,43.43 107.95,27.69 | C3.1 108.71,12.45 107.19,12.45 E3.14 106.93,13.97 107.95,14.99 107.95,27.69
  Top 0.305: 107.95,27.69 108.71,27.69 C5.1 | 107.95,27.69 107.19,27.69 E5.14
  Bottom 0.305: C10.1 52.83,63.25 51.31,63.25 E10.14 51.05,64.77 51.05,69.34 51.56,69.34 52.32,70.1 52.32,77.47 | 52.32,77.47 52.32,78.49 52.83,78.49 R3.2 | 52.32,77.47 42.93,77.47 40.39,74.93 13.97,74.93 U$5.BA2 | E17.14 79.25,98.81 80.77,98.81 C17.1 | E14.14 79.25,81.03 80.77,81.03 C14.1 | E11.14 79.25,63.25 80.77,63.25 C11.1 | E8.14 79.25,45.47 80.77,45.47 C8.1 | E7.14 51.31,45.47 52.83,45.47 C7.1 | E1.14 51.31,12.45 52.83,12.45 C1.1 | U$5.AA2 13.97,4.83 35.05,4.83 C25.1 36.32,4.83 38.35,2.79 52.83,2.79 C24.1 53.85,2.79 61.21,10.16 92.71,10.16 | E21.14 107.19,114.05 108.71,114.05 C21.1 | E15.14 107.19,81.03 108.71,81.03 C15.1 | E12.14 107.19,63.25 108.71,63.25 C12.1 | 92.71,10.16 104.65,10.16 106.17,11.68 E3.14 | 92.71,10.16 92.71,13.97 92.2,14.48 90.68,14.48 90.42,14.22 83.06,14.22 81.79,12.95 C2.1
W1  (via drill 0.71)
  Top 0.305: E18.1 107.19,107.7 107.95,108.46 107.95,115.57 106.68,116.84 106.68,120.65 E21.1 107.19,120.9 109.22,120.9 110.74,119.38 110.74,116.08 111.25,115.57 v111.25,48.01
  Bottom 0.305: v111.25,48.01 102.87,48.01 101.85,46.99 E9.12 | E18.1 106.43,105.41 105.92,104.9 104.39,104.9 103.63,104.14 102.11,104.14 101.35,103.38 92.2,103.38 90.68,101.85 82.55,101.85 82.04,101.35 75.69,101.35 75.44,101.09 71.12,101.09 70.61,101.6 66.55,101.6 66.55,100.58 66.29,100.33 E17.9 65.79,97.79 65.28,97.28 49.02,97.28 41.91,90.17 41.91,87.63 41.4,87.12 39.88,87.12 39.37,87.63 39.37,90.93 33.02,97.28 14.22,97.28 13.97,97.03 U$5.BJ2
W1*W5  (via drill 0.71)
  Top 0.305: E15.6 93.98,87.63 93.98,83.82 92.71,82.55 92.71,80.01 93.22,79.5 93.98,79.5 93.98,72.39 E12.6 93.98,69.85 v93.98,67.56 | v79.76,25.91 79.5,25.65 79.5,21.59 79.25,21.34 E2.1 | v84.07,15.24 84.07,25.4 v84.33,25.65 84.07,26.16 84.07,46.74 84.33,46.99 v84.33,67.56 | v15.24,30.48 13.97,30.48 U$5.AK1
  Bottom 0.305: 67.82,26.16 68.33,26.67 E4.10 | 67.82,26.16 43.94,26.16 43.43,26.67 E6.11 42.93,29.21 42.67,29.46 41.66,29.46 39.88,31.24 16,31.24 v15.24,30.48 | 67.82,26.16 79.5,26.16 v79.76,25.91 80.26,25.65 v84.33,25.65 | v84.07,15.24 84.33,15.49 96.77,15.49 97.28,14.99 97.79,14.99 98.81,13.97 E3.11 | v93.98,67.56 93.73,67.82 84.58,67.82 v84.33,67.56
W1\
  Top 0.305: E4.9 65.79,29.21 64.77,30.23 64.77,38.86 62.23,41.4 62.23,96.77 63.25,97.79 E17.8
W2  (via drill 0.71)
  Top 0.305: v46.99,16.76 46.99,21.59 46.48,22.1 46.48,26.67 46.23,26.92 E6.12 | v64.77,96.27 v64.77,87.12 | v100.33,96.52 100.33,117.86 101.6,119.13 101.6,120.65 E21.3 | v113.79,120.9 112.78,119.89 112.78,89.92 114.05,88.65 114.05,87.12 113.54,86.61 113.54,53.34 114.05,52.83 114.05,51.82 113.03,50.8 113.03,13.97 109.22,10.16 103.63,10.16 102.11,11.68 E3.12
  Bottom 0.305: v46.99,16.76 47.24,17.02 52.58,17.02 53.09,16.51 53.59,16.51 54.1,17.02 80.52,17.02 81.03,16.51 81.53,16.51 81.79,16.76 82.3,16.76 82.55,17.02 98.3,17.02 101.35,13.97 E3.12 | v64.77,87.12 64.77,90.17 65.28,90.68 67.82,90.68 68.33,90.17 E14.5 | v64.77,96.27 65.02,96.52 65.53,96.52 | 65.53,96.52 66.29,97.28 66.8,97.28 67.31,97.79 67.31,100.84 70.36,100.84 70.87,100.33 E17.11 | v100.33,96.52 65.53,96.52 | v113.79,120.9 110.24,120.9 | 110.24,120.9 109.22,120.9 108.46,120.14 102.36,120.14 101.85,120.65 E21.3 | 110.24,120.9 102.87,128.27 13.97,128.27 U$5.BV2
W2\  (via drill 0.71)
  Top 0.305: E2.4 71.63,21.34 72.39,22.1 74.93,22.1 74.93,16.51 72.39,13.97 72.39,11.43 73.66,10.16 83.57,10.16 83.57,13.21 85.09,14.73 85.09,15.75 84.84,16 84.84,24.64 85.34,25.15 85.34,26.16 84.84,26.67 84.84,46.48 85.09,46.74 85.09,66.04 v85.85,66.8 85.34,67.06 85.34,68.07 83.31,70.1 83.31,80.26 83.57,80.52 83.57,91.44 v83.31,91.69
  Bottom 0.305: v85.85,66.8 86.11,67.06 92.96,67.06 93.47,66.55 94.49,66.55 95.76,67.82 108.46,67.82 108.97,67.31 109.47,67.31 110.49,68.33 110.49,68.83 109.47,69.85 108.97,69.85 108.46,69.34 102.36,69.34 101.85,69.85 E12.3 | v83.31,91.69 83.06,91.44 76.71,91.44 75.95,90.68 69.85,90.68 69.85,87.63 69.34,87.12 66.8,87.12 66.29,87.63 E14.6
W3  (via drill 0.71)
  Top 0.305: E2.2 75.69,21.34 75.69,25.91 74.93,26.67 74.93,83.06 75.18,83.31 75.18,86.87 75.69,87.38 75.69,87.88 E14.2 | v17.53,87.63 17.27,87.88 17.27,107.44 17.78,107.95 v17.78,123.7 | v96.01,91.19 95.25,91.95 95.25,117.86 96.52,119.13 96.52,120.65 E21.5
  Bottom 0.305: E14.9 66.29,82.55 70.87,87.12 75.44,87.12 75.95,87.63 E14.2 76.45,90.17 76.96,90.68 96.01,90.68 | 96.01,90.68 103.38,90.68 103.89,90.17 E15.2 | v17.53,87.63 13.97,87.63 U$5.BE2 | v17.78,123.7 18.29,123.7 18.54,123.44 33.02,123.44 34.04,124.46 95,124.46 96.27,123.19 E21.5 | v96.01,91.19 96.01,90.68
W3\  (via drill 0.71)
  Top 0.305: E3.1 106.68,21.59 106.68,25.15 105.41,26.42 105.41,46.99 106.68,48.26 106.68,52.07 E9.1 106.68,54.61 106.68,60.71 105.41,61.98 105.41,64.77 106.68,66.04 106.68,69.85 E12.1 | v54.36,76.71 54.61,76.45 54.61,52.32 53.34,52.32 52.07,51.05 52.07,37.34 51.31,36.58 E6.1
  Bottom 0.305: v54.36,76.71 57.66,80.01 63.25,80.01 E14.8 63.75,80.01 63.75,78.99 64.26,78.49 65.28,78.49 65.53,78.74 72.9,78.74 73.66,77.98 76.45,77.98 76.71,78.23 82.3,78.23 82.8,78.74 84.84,78.74 85.09,78.99 91.19,78.99 91.69,79.5 97.79,79.5 97.79,82.55 98.3,83.06 100.33,83.06 100.33,78.49 106.43,72.39 E12.1
W4  (via drill 0.71)
  Top 0.305: v74.93,102.11 74.93,87.63 74.42,87.12 74.42,83.57 74.17,83.31 74.17,82.3 E14.12 73.66,80.01 v73.66,74.93 | E21.2 103.63,120.9 102.87,120.14 102.87,113.03 104.14,111.76 104.14,107.95 E18.2 | v65.53,59.69 65.53,57.66 64.77,56.9 64.77,47.5 65.53,46.74 E8.9 | v99.06,59.94 99.06,62.23 E12.11 | v14.99,53.34 18.8,49.53 18.8,41.66 19.3,41.15 20.83,41.15 20.83,42.67 20.32,43.18 20.32,56.39 21.08,57.15 21.08,58.17 20.83,58.42 20.83,62.99 19.56,64.26 19.56,80.01 19.3,80.26 19.3,88.39 18.8,88.9 18.8,106.93 19.3,107.44 19.3,122.68 19.56,122.94 v19.56,125.98
  Bottom 0.305: v74.93,102.11 81.79,102.11 82.3,102.62 90.42,102.62 91.95,104.14 101.09,104.14 101.85,104.9 103.38,104.9 103.89,105.41 E18.2 | v65.53,59.69 65.79,59.44 84.07,59.44 84.33,59.69 84.33,63.75 86.36,63.75 87.88,65.28 | 87.88,65.28 94.74,65.28 95.25,64.77 95.25,62.23 95.76,61.72 97.28,61.72 v99.06,59.94 | v14.99,53.34 14.48,52.83 14.22,52.83 13.97,52.58 U$5.AT2 | v19.56,125.98 19.81,125.73 32.26,125.73 33.27,126.75 63.25,126.75 63.5,127 66.04,127 66.29,126.75 88.14,126.75 88.9,127.51 99.57,127.51 103.89,123.19 E21.2 | 87.88,65.28 87.38,65.79 82.55,65.79 80.01,68.33 80.01,68.83 80.26,69.09 80.26,72.9 71.88,72.9 71.37,73.41 71.37,74.93 v73.66,74.93
W4\  (via drill 0.71)
  Top 0.305: 100.33,44.7 100.33,26.42 101.6,25.15 101.6,21.59 E3.3 | 100.33,44.7 100.33,72.39 101.6,73.66 101.6,80.01 E15.12 | v48.77,43.43 48.77,36.58 E6.2 | v83.31,47.5 83.31,20.07 82.8,19.56 82.8,10.92 74.93,10.92 74.17,11.68 E2.12 | 100.33,44.7 99.57,44.7 E9.11
  Bottom 0.305: E9.11 98.81,46.99 98.3,47.5 v83.31,47.5 64.26,47.5 63.75,46.99 E8.8 63.25,44.45 62.74,43.94 49.28,43.94 v48.77,43.43
W5  (via drill 0.71)
  Top 0.305: v78.23,41.15 79.5,42.42 79.5,43.94 80.01,44.45 80.01,45.97 81.53,47.5 81.53,48.26 82.8,49.53 82.8,59.18 82.3,59.69 82.3,61.47 82.8,61.98 82.8,69.6 82.55,69.85 82.55,80.52 82.8,80.77 82.8,88.65 80.26,91.19 80.26,98.55 80.01,98.81 80.01,101.09 79.5,101.6 79.5,104.9 80.26,105.66 v80.26,108.2 | v92.71,126.49 92.71,113.03 93.98,111.76 93.98,107.95 E18.6
  Bottom 0.305: 80.26,108.46 69.34,108.46 68.83,107.95 E17.5 | 80.26,108.46 93.22,108.46 93.73,107.95 E18.6 | v78.23,41.15 78.23,41.66 75.95,43.94 74.42,43.94 73.91,44.45 E8.12 | v80.26,108.2 80.26,108.46 | v92.71,126.49 91.44,125.22 65.79,125.22 65.53,125.48 64.01,125.48 63.75,125.22 33.78,125.22 32.77,124.21 18.8,124.21 18.29,124.71 13.97,124.71 U$5.BU2
W5\  (via drill 0.71)
  Top 0.305: v113.03,52.32 112.78,52.58 112.78,86.87 113.28,87.38 113.28,88.39 112.01,89.66 112.01,115.82 111.51,116.33 111.51,119.63 107.44,123.7 99.57,123.7 99.57,122.94 E21.4 | v60.71,29.97 60.71,39.37 59.69,40.39 59.69,40.89 60.2,41.4 60.2,43.18 60.45,43.43 v60.45,48.26 60.96,48.51 61.47,49.02 v61.47,102.11
  Bottom 0.305: E9.5 96.77,52.07 97.28,51.56 108.46,51.56 109.22,52.32 v113.03,52.32 113.28,51.82 110.24,48.77 102.36,48.77 101.85,49.28 83.57,49.28 82.55,48.26 v60.45,48.26 | v60.71,29.97 62.48,29.97 63.25,29.21 E4.8 | v61.47,102.11 61.47,102.62 63.75,104.9 65.28,104.9 65.79,105.41 E17.6
W6  (via drill 0.71)
  Top 0.305: E21.12 101.6,113.03 101.6,107.95 E18.3 102.11,105.66 102.36,105.41 102.36,103.38 105.41,100.33 105.41,97.79 108.2,95 108.2,87.88 105.92,85.6 105.92,83.06 105.41,82.55 105.41,74.93 102.87,72.39 102.87,65.79 102.11,65.02 102.11,64.52 E12.12 101.09,62.48 101.09,54.36 E9.3 | v35.56,33.02 37.34,31.24 39.88,31.24 40.13,30.99 45.72,30.99 45.72,34.29 E6.3 | v95.25,55.12 95.25,44.45 97.03,42.67 97.03,36.58 E5.5
  Bottom 0.305: E17.2 76.45,105.41 78.99,102.87 81.53,102.87 82.04,103.38 90.17,103.38 91.69,104.9 100.84,104.9 101.35,105.41 E18.3 | v35.56,33.02 35.31,32.77 16.26,32.77 13.97,35.05 U$5.AM2 | E5.5 96.27,36.83 95.76,37.34 75.44,37.34 74.93,36.83 74.93,34.29 74.42,33.78 56.9,33.78 53.34,37.34 46.48,37.34 45.97,36.83 E6.3 | v95.25,55.12 100.84,55.12 101.35,54.61 E9.3
W6\  (via drill 0.71)
  Top 0.305: v89.41,32 89.41,26.16 89.66,25.91 89.66,19.56 92.96,16.26 97.28,16.26 v97.79,16 100.33,18.54 103.63,18.54 103.63,19.3 E3.2 104.14,19.05 104.14,17.53 105.41,16.26 105.41,11.43 105.66,11.18 105.66,10.92 108.97,10.92 112.27,14.22 112.27,48.51 112.01,48.77 112.01,87.63 v112.27,87.88
  Bottom 0.305: v97.79,16 97.54,16.26 82.8,16.26 82.55,16 82.04,16 81.79,15.75 80.77,15.75 80.26,16.26 73.66,16.26 71.37,13.97 E2.11 | v89.41,32 89.66,32.26 90.17,32.26 91.69,33.78 93.22,33.78 93.73,34.29 E5.6 | v112.27,87.88 108.2,87.88 107.44,87.12 102.36,87.12 101.85,87.63 E15.3
W7  (via drill 0.71)
  Top 0.305: 69.85,18.54 67.56,18.54 67.56,18.8 67.31,19.05 67.31,22.1 v66.55,22.86 | 69.85,18.54 72.39,18.54 73.15,19.3 E2.3 | v95,73.91 94.74,74.17 94.74,79.25 95.25,79.76 95.25,87.12 96.01,87.88 E15.5 | v86.87,73.91 86.87,66.29 85.85,65.28 85.85,46.48 85.6,46.23 85.6,26.92 86.11,26.42 86.11,24.89 85.6,24.38 85.6,16.26 85.85,16 85.85,14.48 84.33,12.95 84.33,9.91 83.82,9.4 73.41,9.4 71.88,10.92 70.1,10.92 70.1,11.18 69.85,11.43 69.85,18.54 | v39.37,30.23 39.37,26.67 42.67,23.37 v42.67,22.61
  Bottom 0.305: 93.22,26.16 93.73,26.67 E5.9 | 93.22,26.16 89.92,22.86 v66.55,22.86 66.04,23.11 57.15,23.11 51.82,17.78 43.69,17.78 42.93,18.54 42.42,18.54 41.91,19.05 41.91,21.84 v42.67,22.61 | 93.22,26.16 99.82,26.16 100.33,26.67 100.33,29.21 100.08,29.46 100.08,30.48 103.89,34.29 E5.2 | v95,73.91 94.74,73.66 87.12,73.66 v86.87,73.91 | v39.37,30.23 39.12,30.48 16.76,30.48 15.75,29.46 13.97,29.46 U$5.AK2
W7\  (via drill 0.71)
  Top 0.305: E12.4 98.55,70.1 98.55,69.6 97.79,68.83 97.79,55.12 98.55,54.36 E9.4 98.55,52.32 97.79,51.56 97.79,22.1 | E18.4 99.06,107.95 99.06,113.03 E21.11 | 97.79,22.1 93.73,26.16 91.95,26.16 91.95,26.92 E5.8 | 97.79,22.1 98.55,21.34 E3.4 | v46.99,31.24 46.99,36.83 46.48,37.34 44.45,37.34 43.69,36.58 E6.4
  Bottom 0.305: v46.99,31.24 55.37,31.24 56.39,32.26 78.74,32.26 81.53,29.46 90.93,29.46 91.19,29.21 E5.8 | E18.4 99.57,107.7 100.33,108.46 107.44,108.46 114.81,101.09 114.81,22.1 100.33,22.1 99.57,21.34 E3.4
W8  (via drill 0.71)
  Top 0.305: v55.37,107.19 55.37,68.07 v55.63,67.56 55.37,67.31 v55.37,33.53 55.88,33.27 61.47,27.69 61.47,26.16 61.72,25.91 61.72,18.54 64.77,18.54 65.53,19.3 E2.6 | v15.24,32 13.97,32 U$5.AL1 | v40.64,32 40.64,34.29 E6.5
  Bottom 0.305: E2.6 66.29,19.05 66.8,18.54 79.5,18.54 81.28,20.32 88.65,20.32 90.42,18.54 95.76,18.54 96.27,19.05 E3.5 96.27,21.59 101.35,26.67 E5.12 | 56.13,33.53 55.37,34.29 52.07,34.29 51.56,33.78 41.4,33.78 40.89,34.29 E6.5 | 56.13,33.53 56.64,33.02 74.68,33.02 75.95,34.29 E4.2 | v55.63,67.56 55.88,67.82 62.23,67.82 63.75,69.34 67.82,69.34 68.33,69.85 E11.5 | 56.13,33.53 v55.37,33.53 | v55.37,107.19 56.64,108.46 68.33,108.46 69.09,109.22 93.47,109.22 94.23,108.46 95.76,108.46 96.27,107.95 E18.5 | v15.24,32 v40.64,32
W8\
  Top 0.305: E9.2 103.89,54.61 103.89,61.21 102.87,62.23 102.87,64.77 103.89,65.79 103.89,69.85 E12.2
  Bottom 0.305: 97.54,78.23 99.31,80.01 E15.11 | 97.54,78.23 96.01,76.71 71.12,76.71 66.55,72.14 E11.6 | 97.54,78.23 103.63,72.14 E12.2
W9  (via drill 0.71)
  Top 0.305: E18.11 99.06,97.79 99.06,90.17 E15.4 | v68.33,61.21 68.07,60.96 68.07,54.36 E8.5 | v75.95,78.99 75.69,78.74 75.69,72.14 E11.2 | v27.69,88.9 27.69,82.04 27.94,81.79 27.94,66.04 27.69,65.79 v27.69,49.53
  Bottom 0.305: E18.12 101.09,99.06 99.57,99.06 E18.11 | v68.33,61.21 68.83,61.72 74.42,61.72 74.93,62.23 74.93,69.34 75.44,69.34 75.95,69.85 E11.2 | v75.95,78.99 82.04,78.99 88.65,85.6 90.17,85.6 91.69,87.12 98.3,87.12 98.81,87.63 E15.4 | v27.69,88.9 13.97,88.9 U$5.BF2 | v27.69,49.53 27.94,49.78 31.75,49.78 32,50.04 51.56,50.04 52.83,48.77 53.85,48.77 54.1,49.02 54.61,49.02 54.86,49.28 64.01,49.28 64.26,49.02 65.28,49.02 68.33,52.07 E8.5
W9\  (via drill 0.71)
  Top 0.305: v42.16,32 41.91,32.26 41.91,37.34 39.37,37.34 38.61,36.58 E6.6 | v96.52,74.93 96.52,72.39 E12.5 | v72.39,73.91 v72.39,55.12 72.39,44.45 74.17,42.67 74.17,36.58 E4.3 73.66,34.29 v73.66,30.73 73.15,30.48 72.39,29.72 72.39,24.64 69.09,21.34 E2.5
  Bottom 0.305: E8.6 66.29,54.61 66.8,55.12 v72.39,55.12 93.22,55.12 93.73,54.61 E9.6 | E3.6 93.73,21.59 93.22,22.1 69.34,22.1 68.83,21.59 E2.5 | v42.16,32 43.94,30.23 47.5,30.23 47.75,30.48 59.69,30.48 60.2,30.99 61.21,30.99 61.47,30.73 v73.66,30.73 | v96.52,74.93 86.36,74.93 85.09,73.66 72.64,73.66 v72.39,73.91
